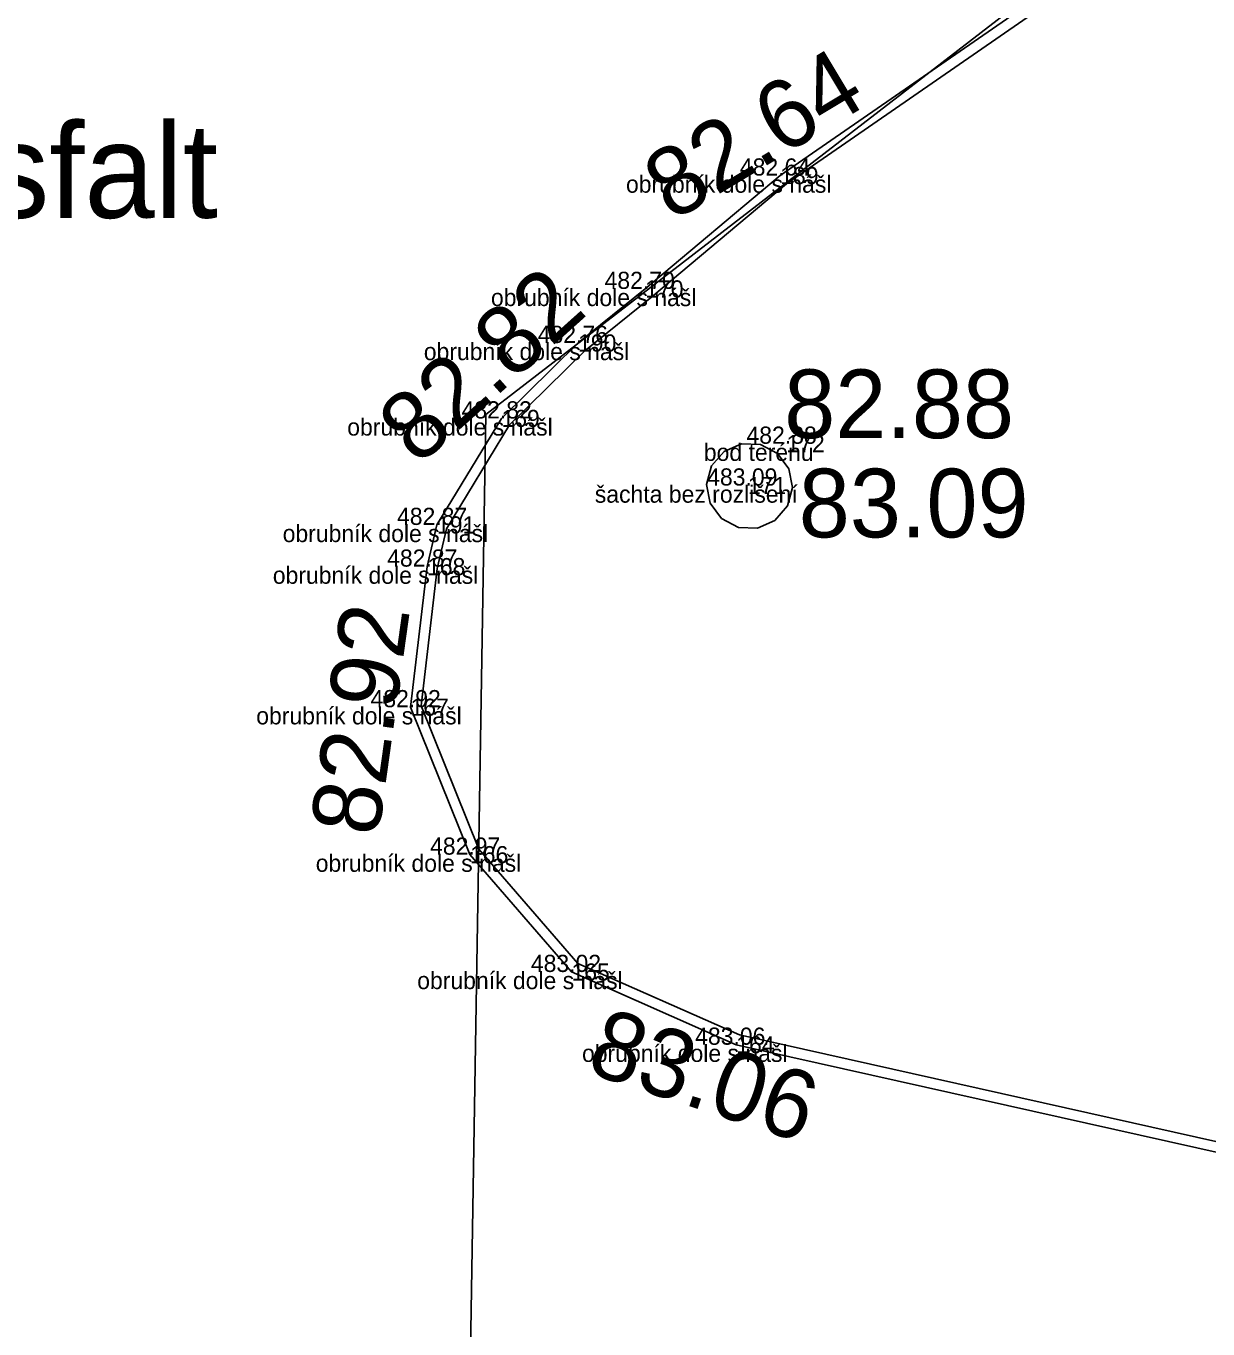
# Model space of a CAD drawing. Extents: x -888468 to -888310, y -1023047 to -1022832.
# Drawn here: x -888391.81 to -888378.04, y -1022875.57 to -1022860.39 of the extents above; entities that cross this region are included whole.
import ezdxf

# ---------------------------------------------------------------- set-up
doc = ezdxf.new("R2010")
doc.units = 0
for name, color, linetype in [('035-spod', 7, 'Continuous'), ('4 obrubník dole', 7, 'Continuous'), ('52 šachta bez rozlišení', 7, 'Continuous'), ('83 semafor', 7, 'Continuous'), ('bod', 7, 'Continuous'), ('bod kod', 7, 'Continuous'), ('bod výška', 7, 'Continuous'), ('bod číslo', 7, 'Continuous'), ('KN stav', 7, 'Continuous'), ('Nadmořská výška TISK', 7, 'Continuous'), ('popisy', 7, 'Continuous')]:
    doc.layers.add(name, color=color, linetype=linetype)

msp = doc.modelspace()

# ---------------------------------------------------------------- linework, layer by layer
at = {"layer": '035-spod'}
for p, q in [((-888383.021, -1022862.134), (-888383.021, -1022862.134)), ((-888383.021, -1022862.134), (-888383.021, -1022862.134)), ((-888383.021, -1022862.134), (-888383.021, -1022862.134)), ((-888383.021, -1022862.134), (-888383.021, -1022862.134)), ((-888384.594, -1022863.455), (-888384.594, -1022863.455)), ((-888384.594, -1022863.455), (-888384.594, -1022863.455)), ((-888384.594, -1022863.455), (-888384.594, -1022863.455)), ((-888384.594, -1022863.455), (-888384.594, -1022863.455)), ((-888385.376, -1022864.085), (-888385.376, -1022864.085)), ((-888385.376, -1022864.085), (-888385.376, -1022864.085)), ((-888385.376, -1022864.085), (-888385.376, -1022864.085)), ((-888385.376, -1022864.085), (-888385.376, -1022864.085)), ((-888386.268, -1022864.964), (-888386.268, -1022864.964)), ((-888386.268, -1022864.964), (-888386.268, -1022864.964)), ((-888386.268, -1022864.964), (-888386.268, -1022864.964)), ((-888386.268, -1022864.964), (-888386.268, -1022864.964)), ((-888382.949, -1022865.259), (-888382.949, -1022865.259)), ((-888382.949, -1022865.259), (-888382.949, -1022865.259)), ((-888382.949, -1022865.259), (-888382.949, -1022865.259)), ((-888382.949, -1022865.259), (-888382.949, -1022865.259)), ((-888383.398, -1022865.746), (-888383.398, -1022865.746)), ((-888383.398, -1022865.746), (-888383.398, -1022865.746)), ((-888383.398, -1022865.746), (-888383.398, -1022865.746)), ((-888383.398, -1022865.746), (-888383.398, -1022865.746)), ((-888387.02, -1022866.205), (-888387.02, -1022866.205)), ((-888387.02, -1022866.205), (-888387.02, -1022866.205)), ((-888387.02, -1022866.205), (-888387.02, -1022866.205)), ((-888387.02, -1022866.205), (-888387.02, -1022866.205)), ((-888387.135, -1022866.691), (-888387.135, -1022866.691)), ((-888387.135, -1022866.691), (-888387.135, -1022866.691)), ((-888387.135, -1022866.691), (-888387.135, -1022866.691)), ((-888387.135, -1022866.691), (-888387.135, -1022866.691)), ((-888387.328, -1022868.329), (-888387.328, -1022868.329)), ((-888387.328, -1022868.329), (-888387.328, -1022868.329)), ((-888387.328, -1022868.329), (-888387.328, -1022868.329)), ((-888387.328, -1022868.329), (-888387.328, -1022868.329)), ((-888386.635, -1022870.047), (-888386.635, -1022870.047)), ((-888386.635, -1022870.047), (-888386.635, -1022870.047)), ((-888386.635, -1022870.047), (-888386.635, -1022870.047)), ((-888386.635, -1022870.047), (-888386.635, -1022870.047)), ((-888385.453, -1022871.414), (-888385.453, -1022871.414)), ((-888385.453, -1022871.414), (-888385.453, -1022871.414)), ((-888385.453, -1022871.414), (-888385.453, -1022871.414)), ((-888385.453, -1022871.414), (-888385.453, -1022871.414)), ((-888383.533, -1022872.262), (-888383.533, -1022872.262)), ((-888383.533, -1022872.262), (-888383.533, -1022872.262)), ((-888383.533, -1022872.262), (-888383.533, -1022872.262)), ((-888383.533, -1022872.262), (-888383.533, -1022872.262))]:
    msp.add_line(p, q, dxfattribs=at)
at = {"layer": '4 obrubník dole'}
for points in [[(-888355.066, -1022852.699), (-888361.16, -1022852.766), (-888366.975, -1022853.756), (-888371.578, -1022855.426), (-888375.828, -1022857.464), (-888379.04, -1022859.379), (-888383.021, -1022862.134), (-888384.594, -1022863.455), (-888385.376, -1022864.085), (-888386.268, -1022864.964), (-888387.02, -1022866.205), (-888387.135, -1022866.691), (-888387.328, -1022868.329), (-888386.635, -1022870.047), (-888385.453, -1022871.414), (-888383.533, -1022872.262), (-888375.666, -1022874.022)], [(-888355.067, -1022852.819), (-888361.149, -1022852.886), (-888366.944, -1022853.872), (-888371.531, -1022855.537), (-888375.771, -1022857.57), (-888378.975, -1022859.48), (-888382.948, -1022862.229), (-888384.518, -1022863.548), (-888385.296, -1022864.175), (-888386.173, -1022865.039), (-888386.908, -1022866.251), (-888387.017, -1022866.712), (-888387.205, -1022868.313), (-888386.531, -1022869.984), (-888385.38, -1022871.315), (-888383.495, -1022872.147), (-888375.64, -1022873.905)]]:
    msp.add_lwpolyline(points, dxfattribs=at)
at = {"layer": '52 šachta bez rozlišení'}
for p, q in [((-888383.821, -1022865.517), (-888383.676, -1022865.349)), ((-888383.676, -1022865.349), (-888383.472, -1022865.259)), ((-888383.472, -1022865.259), (-888383.25, -1022865.268)), ((-888383.25, -1022865.268), (-888383.053, -1022865.372)), ((-888383.879, -1022865.732), (-888383.821, -1022865.517)), ((-888383.053, -1022865.372), (-888382.921, -1022865.551)), ((-888382.921, -1022865.551), (-888382.879, -1022865.77)), ((-888383.838, -1022865.951), (-888383.879, -1022865.732)), ((-888382.879, -1022865.77), (-888382.937, -1022865.984)), ((-888383.705, -1022866.13), (-888383.838, -1022865.951)), ((-888382.937, -1022865.984), (-888383.082, -1022866.153)), ((-888383.509, -1022866.234), (-888383.705, -1022866.13)), ((-888383.286, -1022866.242), (-888383.509, -1022866.234)), ((-888383.082, -1022866.153), (-888383.286, -1022866.242))]:
    msp.add_line(p, q, dxfattribs=at)
at = {"layer": '83 semafor'}
for p, q in [((-888383.021, -1022862.134), (-888383.021, -1022862.134)), ((-888384.594, -1022863.455), (-888384.594, -1022863.455)), ((-888385.376, -1022864.085), (-888385.376, -1022864.085)), ((-888386.268, -1022864.964), (-888386.268, -1022864.964)), ((-888382.949, -1022865.259), (-888382.949, -1022865.259)), ((-888383.398, -1022865.746), (-888383.398, -1022865.746)), ((-888387.02, -1022866.205), (-888387.02, -1022866.205)), ((-888387.135, -1022866.691), (-888387.135, -1022866.691)), ((-888387.328, -1022868.329), (-888387.328, -1022868.329)), ((-888386.635, -1022870.047), (-888386.635, -1022870.047)), ((-888385.453, -1022871.414), (-888385.453, -1022871.414)), ((-888383.533, -1022872.262), (-888383.533, -1022872.262))]:
    msp.add_line(p, q, dxfattribs=at)
at = {"layer": 'bod'}
for p, q in [((-888383.021, -1022862.134), (-888383.021, -1022862.134)), ((-888384.594, -1022863.455), (-888384.594, -1022863.455)), ((-888385.376, -1022864.085), (-888385.376, -1022864.085)), ((-888386.268, -1022864.964), (-888386.268, -1022864.964)), ((-888382.949, -1022865.259), (-888382.949, -1022865.259)), ((-888383.398, -1022865.746), (-888383.398, -1022865.746)), ((-888387.02, -1022866.205), (-888387.02, -1022866.205)), ((-888387.135, -1022866.691), (-888387.135, -1022866.691)), ((-888387.328, -1022868.329), (-888387.328, -1022868.329)), ((-888386.635, -1022870.047), (-888386.635, -1022870.047)), ((-888385.453, -1022871.414), (-888385.453, -1022871.414)), ((-888383.533, -1022872.262), (-888383.533, -1022872.262))]:
    msp.add_line(p, q, dxfattribs=at)
at = {"layer": 'KN stav'}
msp.add_lwpolyline([(-888395.921, -1022831.642), (-888366.39, -1022840.38), (-888371, -1022854.84), (-888379.9, -1022859.86), (-888386.45, -1022864.92), (-888386.7, -1022880.1), (-888389.13, -1022894.87), (-888391.86, -1022903.43), (-888393.66, -1022903.02), (-888399.68, -1022922.16), (-888387.05, -1022926.87), (-888374.19, -1022930.1), (-888372.02, -1022930.99), (-888351.3, -1022937.61), (-888350.91, -1022937.53), (-888346.06, -1022939.2)], dxfattribs=at)

# ---------------------------------------------------------------- texts
at = {"layer": 'bod kod'}
for s, p in [('obrubník dole s nášl', (-888384.818, -1022862.334)), ('obrubník dole s nášl', (-888386.391, -1022863.655)), ('obrubník dole s nášl', (-888387.173, -1022864.285)), ('obrubník dole s nášl', (-888388.065, -1022865.164)), ('bod terénu', (-888383.911, -1022865.459)), ('šachta bez rozlišení', (-888385.181, -1022865.946)), ('obrubník dole s nášl', (-888388.817, -1022866.405)), ('obrubník dole s nášl', (-888388.932, -1022866.891)), ('obrubník dole s nášl', (-888389.125, -1022868.529)), ('obrubník dole s nášl', (-888388.432, -1022870.247)), ('obrubník dole s nášl', (-888387.25, -1022871.614)), ('obrubník dole s nášl', (-888385.33, -1022872.462))]:
    msp.add_text(s, height=0.2, dxfattribs=at).set_placement(p)
at = {"layer": 'bod výška'}
for s, p in [('482.64', (-888383.491, -1022862.134)), ('482.70', (-888385.067, -1022863.455)), ('482.76', (-888385.846, -1022864.085)), ('482.82', (-888386.733, -1022864.964)), ('482.88', (-888383.414, -1022865.259)), ('483.09', (-888383.872, -1022865.746)), ('482.87', (-888387.485, -1022866.205)), ('482.87', (-888387.6, -1022866.691)), ('482.92', (-888387.793, -1022868.329)), ('482.97', (-888387.1, -1022870.047)), ('483.02', (-888385.926, -1022871.414)), ('483.06', (-888384.012, -1022872.262))]:
    msp.add_text(s, height=0.2, dxfattribs=at).set_placement(p)
at = {"layer": 'bod číslo'}
for s, p in [('189', (-888383.021, -1022862.234)), ('170', (-888384.594, -1022863.555)), ('190', (-888385.376, -1022864.185)), ('169', (-888386.268, -1022865.064)), ('172', (-888382.949, -1022865.359)), ('171', (-888383.398, -1022865.846)), ('191', (-888387.02, -1022866.305)), ('168', (-888387.135, -1022866.791)), ('167', (-888387.328, -1022868.429)), ('166', (-888386.635, -1022870.147)), ('165', (-888385.453, -1022871.514)), ('164', (-888383.533, -1022872.362))]:
    msp.add_text(s, height=0.2, dxfattribs=at).set_placement(p)
at = {"layer": 'Nadmořská výška TISK'}
for s, rotation, p in [('82.64', 30.9958, (-888384.279, -1022862.678)), ('82.82', 41.93, (-888387.239, -1022865.528)), ('82.92', 82.0299, (-888387.705, -1022869.847)), ('83.06', 341.8273, (-888385.303, -1022872.576))]:
    msp.add_text(s, height=0.8, rotation=rotation, dxfattribs=at).set_placement(p)
for s, p in [('82.88', (-888382.975, -1022865.194)), ('83.09', (-888382.805, -1022866.35))]:
    msp.add_text(s, height=0.8, dxfattribs=at).set_placement(p)
at = {"layer": 'popisy'}
msp.add_text('asfalt', height=1.1016, dxfattribs=at).set_placement((-888393.092, -1022862.627))

doc.saveas('drawing.dxf')
